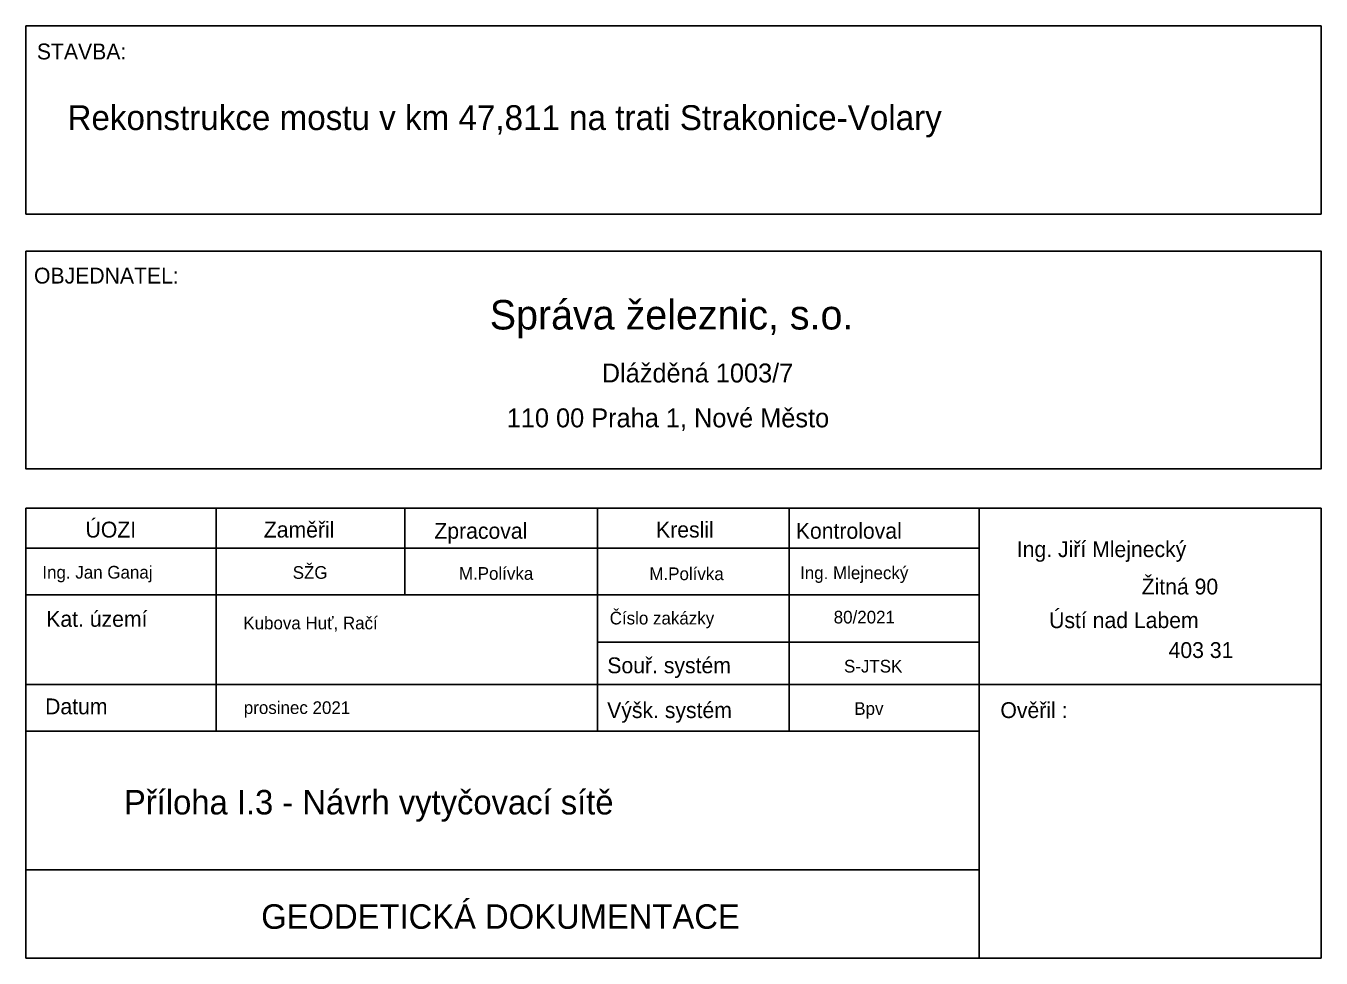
# Model space of a CAD drawing. Extents: x -879530 to -879371, y -1019242 to -1019127.
import ezdxf

# ---------------------------------------------------------------- set-up
doc = ezdxf.new("R2010")
doc.units = 0
doc.layers.add('tabulka', color=7, linetype='Continuous')

msp = doc.modelspace()

# ---------------------------------------------------------------- linework, layer by layer
at = {"layer": 'tabulka'}
for p, q in [((-879530.09, -1019186.45), (-879371.44, -1019186.45)), ((-879506.8, -1019186.45), (-879506.8, -1019213.77)), ((-879483.66, -1019186.45), (-879483.66, -1019197.07)), ((-879460.06, -1019186.45), (-879460.06, -1019213.77)), ((-879436.61, -1019186.45), (-879436.61, -1019213.77)), ((-879413.31, -1019241.58), (-879413.31, -1019186.45)), ((-879530.09, -1019191.36), (-879413.31, -1019191.36)), ((-879530.09, -1019197.07), (-879413.31, -1019197.07)), ((-879460.06, -1019202.88), (-879413.31, -1019202.88)), ((-879530.09, -1019208.07), (-879371.44, -1019208.07)), ((-879530.09, -1019213.77), (-879413.31, -1019213.77)), ((-879530.09, -1019230.76), (-879413.31, -1019230.76))]:
    msp.add_line(p, q, dxfattribs=at)
for points in [[(-879530.09, -1019127.36), (-879371.44, -1019127.36), (-879371.44, -1019150.43), (-879530.09, -1019150.43)], [(-879530.09, -1019154.95), (-879371.44, -1019154.95), (-879371.44, -1019181.64), (-879530.09, -1019181.64)]]:
    msp.add_lwpolyline(points, close=True, dxfattribs=at)
msp.add_lwpolyline([(-879371.44, -1019186.45), (-879371.44, -1019241.58), (-879530.09, -1019241.58), (-879530.09, -1019186.45)], dxfattribs=at)

# ---------------------------------------------------------------- texts
for s, height, p in [('STAVBA:', 1.94, (-879528.75, -1019131.47)), ('Rekonstrukce mostu v km 47,811 na trati Strakonice-Volary', 3.04, (-879525, -1019140.12)), ('OBJEDNATEL:', 1.94, (-879529.1, -1019158.93)), ('Správa železnic, s.o.', 3.61, (-879473.27, -1019164.56)), ('Dlážděná 1003/7', 2.32, (-879459.55, -1019171.05)), ('110 00 Praha 1, Nové Město', 2.32, (-879471.19, -1019176.55)), ('ÚOZI', 1.94, (-879522.79, -1019190.05)), ('Zaměřil', 1.94, (-879500.95, -1019190.05)), ('Zpracoval', 1.94, (-879480.06, -1019190.2)), ('Kreslil', 1.94, (-879452.9, -1019190.05)), ('Kontroloval', 1.94, (-879435.78, -1019190.2)), ('Ing. Jiří Mlejnecký', 1.94, (-879408.71, -1019192.45)), ('Ing. Jan Ganaj', 1.552, (-879528.08, -1019195.08)), ('SŽG', 1.552, (-879497.41, -1019195.11)), ('M.Polívka', 1.552, (-879477.05, -1019195.23)), ('M.Polívka', 1.552, (-879453.72, -1019195.27)), ('Ing. Mlejnecký', 1.552, (-879435.26, -1019195.15)), ('Žitná 90', 1.94, (-879393.42, -1019197.03)), ('Kat. území', 1.94, (-879527.6, -1019200.99)), ('Kubova Huť, Račí', 1.552, (-879503.46, -1019201.3)), ('Číslo zakázky', 1.552, (-879458.58, -1019200.7)), ('80/2021', 1.552, (-879431.14, -1019200.58)), ('Ústí nad Labem', 1.94, (-879404.75, -1019201.15)), ('403 31', 1.94, (-879390.12, -1019204.81)), ('Souř. systém', 1.94, (-879458.87, -1019206.68)), ('S-JTSK', 1.552, (-879429.88, -1019206.59)), ('Datum', 1.94, (-879527.74, -1019211.71)), ('prosinec 2021', 1.552, (-879503.4, -1019211.67)), ('Výšk. systém', 1.94, (-879458.89, -1019212.17)), ('Bpv', 1.552, (-879428.62, -1019211.78)), ('Ověřil :', 1.94, (-879410.72, -1019212.17)), ('Příloha I.3 - Návrh vytyčovací sítě', 3, (-879518.08, -1019223.98)), ('GEODETICKÁ DOKUMENTACE ', 3, (-879501.27, -1019237.99))]:
    msp.add_text(s, height=height, dxfattribs=at).set_placement(p)

doc.saveas('drawing.dxf')
